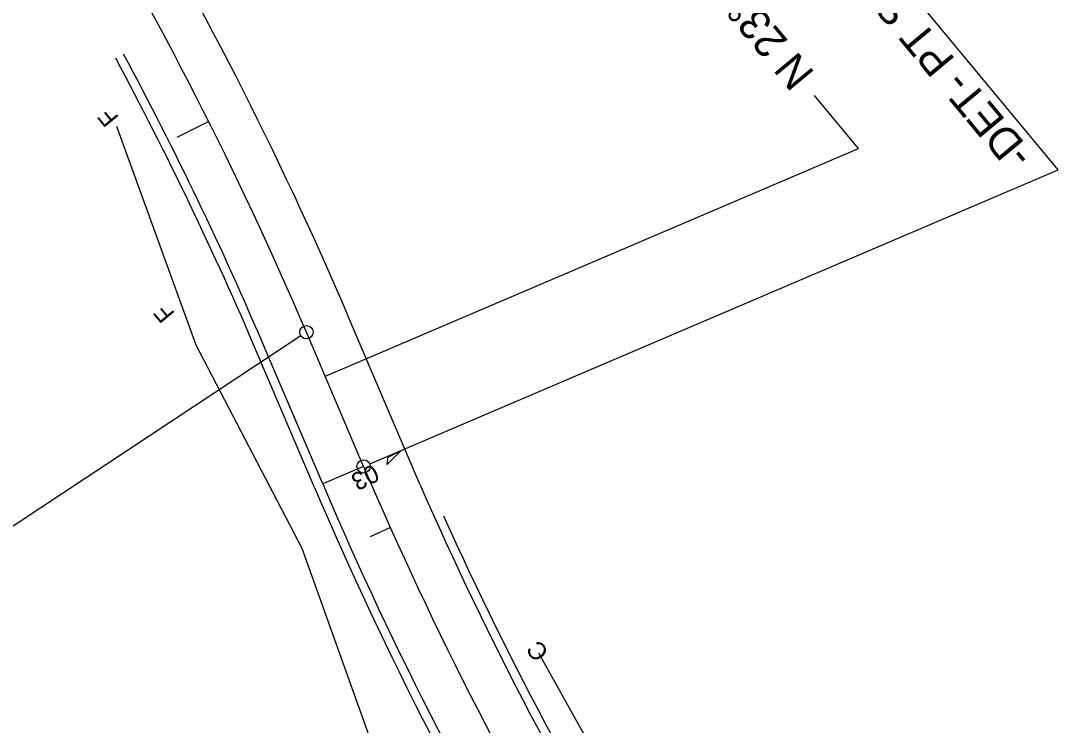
# Model space of a CAD drawing. Extents: x 2597390 to 2598563, y 852595 to 853909.
# Drawn here: x 2597727.6 to 2597960.9, y 853471.1 to 853629.4 of the extents above; entities that cross this region are included whole.
import ezdxf

# ---------------------------------------------------------------- set-up
doc = ezdxf.new("R2010")
doc.units = 0
for name, color, linetype in [('Prop EOT', 7, 'Continuous'), ('Prop Horizontal Alignment', 7, 'Continuous'), ('Prop Horizontal Alignment Direction Label', 7, 'Continuous'), ('Prop Horizontal Alignment Station Label', 7, 'Continuous'), ('Prop Horizontal Alignment Tick Large', 7, 'Continuous'), ('Prop Horizontal Alignment Tick Small', 7, 'Continuous'), ('Prop Lane Lines', 7, 'Continuous'), ('Prop Paved Shoulder', 7, 'Continuous'), ('Prop SS Fill Line', 7, 'Continuous'), ('Prop SS Misc', 7, 'Continuous'), ('Prop SS Transition Line', 7, 'Continuous'), ('Prop Superelevation  Arrow CELL', 7, 'Continuous'), ('Prop Superelevation Label', 7, 'Continuous')]:
    doc.layers.add(name, color=color, linetype=linetype)

msp = doc.modelspace()

# ---------------------------------------------------------------- linework, layer by layer
at = {"layer": 'Prop EOT'}
msp.add_line((2597795.48, 853525.31), (2597782.62, 853555.45), dxfattribs=at)
for centre, radius, start, end in [((2597025.61, 853232.56), 823, 23.10033, 28.23175), ((2598570.89, 853856.05), 843, 203.10033, 219.70669), ((2598570.89, 853856.05), 823, 203.70219, 219.70669)]:
    msp.add_arc(centre, radius, start, end, dxfattribs=at)
at = {"layer": 'Prop Horizontal Alignment'}
msp.add_line((2597804.68, 853529.23), (2597791.82, 853559.38), dxfattribs=at)
for centre, start, end in [((2597025.61, 853232.56), 23.10033, 31.1561), ((2598570.89, 853856.05), 203.10033, 219.70669)]:
    msp.add_arc(centre, 833, start, end, dxfattribs=at)
at = {"layer": 'Prop Horizontal Alignment Direction Label'}
for p, q in [((2597915.96, 853600.66), (2597906.06, 853612.58)), ((2597796.27, 853549.6), (2597915.96, 853600.66))]:
    msp.add_line(p, q, dxfattribs=at)
at = {"layer": 'Prop Horizontal Alignment Station Label'}
for p, q in [((2597960.9, 853595.87), (2597880.7, 853692.45)), ((2597806.06, 853529.82), (2597960.9, 853595.87)), ((2597790.57, 853558.55), (2597623.9, 853448.45))]:
    msp.add_line(p, q, dxfattribs=at)
for centre in [(2597791.82, 853559.38), (2597804.68, 853529.23)]:
    msp.add_circle(centre, 1.5, dxfattribs=at)
at = {"layer": 'Prop Horizontal Alignment Tick Large'}
msp.add_line((2597769.85, 853606.72), (2597762.7, 853603.13), dxfattribs=at)
at = {"layer": 'Prop Horizontal Alignment Tick Small'}
msp.add_line((2597810.7, 853515.47), (2597806.14, 853513.42), dxfattribs=at)
at = {"layer": 'Prop Lane Lines'}
msp.add_line((2597817.31, 853525.22), (2597801.06, 853563.32), dxfattribs=at)
msp.add_arc((2597025.61, 853232.56), 843.05, 23.10033, 31.1561, dxfattribs=at)
at = {"layer": 'Prop Paved Shoulder'}
msp.add_line((2597793.64, 853524.52), (2597780.78, 853554.67), dxfattribs=at)
for centre, radius, start, end in [((2597025.61, 853232.56), 821, 23.10033, 28.23175), ((2598570.89, 853856.05), 845, 203.10033, 219.70669), ((2598570.89, 853856.05), 821, 204.30663, 219.70669)]:
    msp.add_arc(centre, radius, start, end, dxfattribs=at)
at = {"layer": 'Prop SS Fill Line'}
for p, q in [((2597767.01, 853556.45), (2597749.17, 853605.61)), ((2597790.88, 853510.78), (2597767.01, 853556.45)), ((2597809.03, 853460.11), (2597790.88, 853510.78))]:
    msp.add_line(p, q, dxfattribs=at)
at = {"layer": 'Prop SS Transition Line'}
for p, q in [((2597787.08, 853570.28), (2597787.08, 853570.28)), ((2597869.06, 853442.65), (2597844.08, 853487.3))]:
    msp.add_line(p, q, dxfattribs=at)
at = {"layer": 'Prop Superelevation  Arrow CELL'}
msp.add_lwpolyline([(2597813.12, 853532.78), (2597810, 853529.64), (2597810.23, 853531.33)], close=True, dxfattribs=at)
at = {"layer": 'Prop Superelevation Label'}
msp.add_line((2597804.68, 853529.23), (2597795.48, 853525.31), dxfattribs=at)

# ---------------------------------------------------------------- texts
at = {"layer": 'Prop Horizontal Alignment Direction Label'}
msp.add_text('N 23%%d 06\' 01.2" W', height=7, rotation=129.7067, dxfattribs=at).set_placement((2597906.32, 853617.57))
at = {"layer": 'Prop Horizontal Alignment Station Label'}
msp.add_text('-DET- PT Sta.  19+15.02', height=7, rotation=129.7067, dxfattribs=at).set_placement((2597955.53, 853599.39))
at = {"layer": 'Prop SS Misc'}
for s, rotation, p in [('F', 129.4254, (2597749.81, 853607.63)), ('F', 129.4254, (2597762.4, 853563.59)), ('C', 127.8004, (2597846.53, 853487.41))]:
    msp.add_text(s, height=4, rotation=rotation, dxfattribs=at).set_placement(p)
at = {"layer": 'Prop Superelevation Label'}
msp.add_text('03', height=4, rotation=206.5395, dxfattribs=at).set_placement((2597806.83, 853529.86))

doc.saveas('drawing.dxf')
